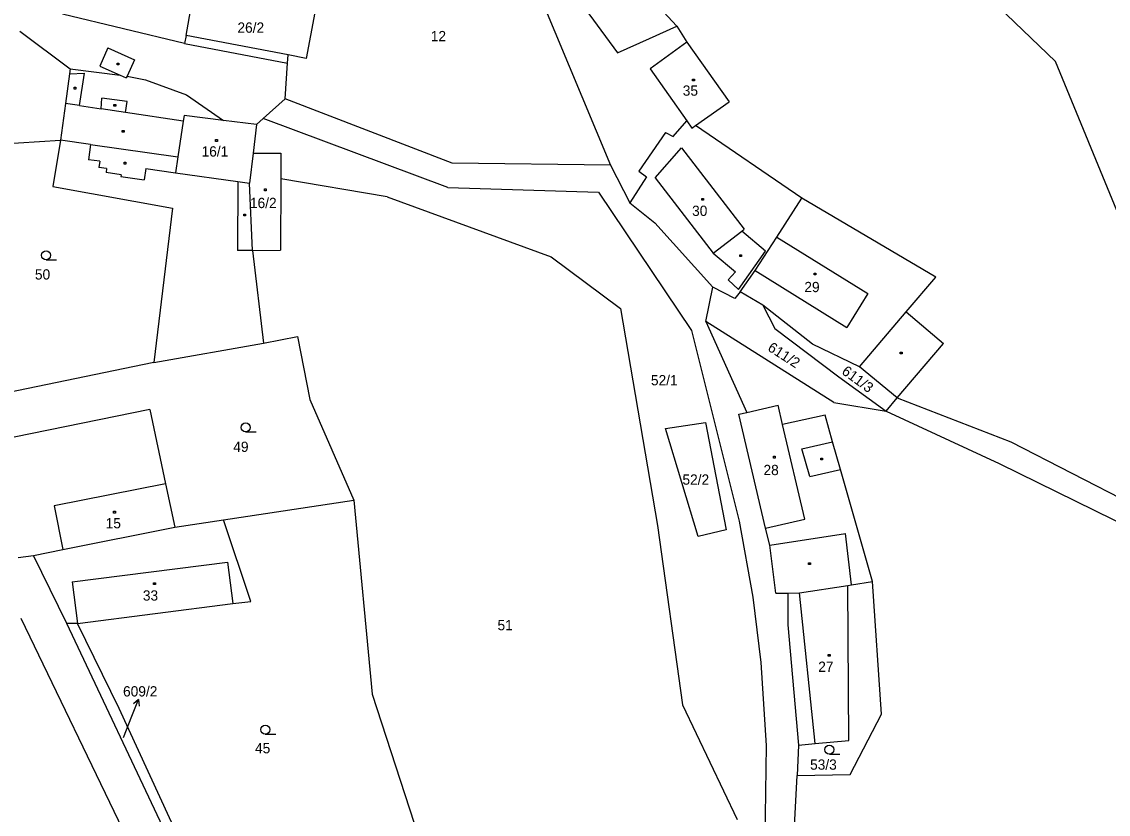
# Model space of a CAD drawing. Extents: x -794421 to -792735, y -1117671 to -1115559.
# Drawn here: x -793289.6 to -793109.5, y -1117055.3 to -1116924 of the extents above; entities that cross this region are included whole.
import ezdxf

# ---------------------------------------------------------------- set-up
doc = ezdxf.new("R2010")
doc.units = 0
for name, color, linetype in [('Komunikace', 7, 'Continuous'), ('Vrstva 1', 7, 'Continuous'), ('Vrstva 14', 7, 'Continuous'), ('Vrstva 15', 7, 'Continuous'), ('Vrstva 16', 7, 'Continuous'), ('Vrstva 2', 7, 'Continuous'), ('Vrstva 23', 7, 'Continuous'), ('Vrstva 25', 7, 'Continuous')]:
    doc.layers.add(name, color=color, linetype=linetype)

msp = doc.modelspace()

# ---------------------------------------------------------------- linework, layer by layer
at = {"layer": 'Komunikace'}
msp.add_line((-793272.71, -1117042.6), (-793271.32, -1117039.06), dxfattribs=at)
at = {"layer": 'Vrstva 1'}
for p, q in [((-793180.98, -1116924.73), (-793191.3, -1116913.51)), ((-793200.57, -1116915.82), (-793190.84, -1116929.15)), ((-793203.93, -1116919.16), (-793192.01, -1116947.74)), ((-793118.24, -1116930.56), (-793129.06, -1116920.12)), ((-793262.33, -1116926.27), (-793261.41, -1116921.2)), ((-793241, -1116922.43), (-793242.42, -1116930.04)), ((-793262.58, -1116927.59), (-793282.79, -1116922.72)), ((-793289.85, -1116925.54), (-793281.55, -1116931.8)), ((-793185.53, -1116926.77), (-793180.98, -1116924.73)), ((-793180.98, -1116924.73), (-793179.36, -1116927.35)), ((-793262.33, -1116926.27), (-793262.58, -1116927.59)), ((-793262.58, -1116927.59), (-793245.52, -1116930.82)), ((-793190.84, -1116929.15), (-793185.53, -1116926.77)), ((-793179.36, -1116927.35), (-793185.44, -1116931.78)), ((-793179.36, -1116927.35), (-793172.35, -1116937.22)), ((-793275.29, -1116928.32), (-793276.62, -1116931.34)), ((-793275.29, -1116928.32), (-793270.88, -1116930.27)), ((-793245.52, -1116930.82), (-793245.43, -1116929.47)), ((-793242.42, -1116930.04), (-793245.43, -1116929.47)), ((-793276.62, -1116931.34), (-793273.25, -1116932.83)), ((-793270.88, -1116930.27), (-793272.1, -1116932.97)), ((-793245.9, -1116936.77), (-793245.52, -1116930.82)), ((-793107.29, -1116957.14), (-793118.24, -1116930.56)), ((-793281.62, -1116932.62), (-793282.31, -1116937.53)), ((-793281.55, -1116931.8), (-793281.62, -1116932.62)), ((-793281.55, -1116931.8), (-793273.25, -1116932.83)), ((-793272.1, -1116932.97), (-793269.06, -1116933.59)), ((-793185.44, -1116931.78), (-793179.36, -1116940.37)), ((-793269.06, -1116933.59), (-793262.27, -1116936.09)), ((-793262.27, -1116936.09), (-793256.1, -1116940.31)), ((-793249.53, -1116940), (-793245.9, -1116936.77)), ((-793218.24, -1116947.4), (-793245.9, -1116936.77)), ((-793282.31, -1116937.53), (-793283.16, -1116943.6)), ((-793177.91, -1116941.15), (-793172.35, -1116937.22)), ((-793250.64, -1116940.98), (-793256.1, -1116940.31)), ((-793250.64, -1116940.98), (-793249.53, -1116940)), ((-793218.93, -1116951.43), (-793249.53, -1116940)), ((-793181.61, -1116943), (-793179.36, -1116940.37)), ((-793179.36, -1116940.37), (-793178.51, -1116941.58)), ((-793250.64, -1116940.98), (-793251.22, -1116945.75)), ((-793178.51, -1116941.58), (-793177.91, -1116941.15)), ((-793160.26, -1116953.21), (-793177.91, -1116941.15)), ((-793313.1, -1116945.43), (-793283.16, -1116943.6)), ((-793283.16, -1116943.6), (-793284.43, -1116951.26)), ((-793182.85, -1116942.31), (-793187.32, -1116948.72)), ((-793182.85, -1116942.31), (-793181.61, -1116943)), ((-793251.22, -1116945.75), (-793251.82, -1116950.7)), ((-793251.22, -1116945.75), (-793246.61, -1116945.77)), ((-793246.61, -1116945.77), (-793246.63, -1116949.98)), ((-793192.01, -1116947.74), (-793218.24, -1116947.4)), ((-793192.01, -1116947.74), (-793188.78, -1116953.98)), ((-793187.32, -1116948.72), (-793186.03, -1116949.69)), ((-793284.43, -1116951.26), (-793264.58, -1116954.85)), ((-793251.29, -1116961.86), (-793251.82, -1116950.7)), ((-793246.63, -1116949.98), (-793246.69, -1116961.83)), ((-793228.99, -1116952.96), (-793246.63, -1116949.98)), ((-793186.03, -1116949.69), (-793188.78, -1116953.98)), ((-793228.99, -1116952.96), (-793201.81, -1116962.93)), ((-793218.93, -1116951.43), (-793193.99, -1116952.19)), ((-793193.99, -1116952.19), (-793178.57, -1116975.15)), ((-793264.58, -1116954.85), (-793267.65, -1116980.42)), ((-793188.78, -1116953.98), (-793184.63, -1116957.3)), ((-793164.45, -1116959.67), (-793160.26, -1116953.21)), ((-793138.07, -1116966.28), (-793160.26, -1116953.21)), ((-793184.63, -1116957.3), (-793175.02, -1116967.94)), ((-793168.03, -1116965.2), (-793164.45, -1116959.67)), ((-793251.29, -1116961.86), (-793246.69, -1116961.83)), ((-793251.29, -1116961.86), (-793249.49, -1116977.21)), ((-793201.81, -1116962.93), (-793190.35, -1116971.51)), ((-793170.49, -1116968.71), (-793168.03, -1116965.2)), ((-793142.98, -1116972.07), (-793138.07, -1116966.28)), ((-793176.21, -1116973.63), (-793175.02, -1116967.94)), ((-793171.36, -1116969.86), (-793175.02, -1116967.94)), ((-793170.49, -1116968.71), (-793171.36, -1116969.86)), ((-793166.76, -1116970.96), (-793170.49, -1116968.71)), ((-793166.76, -1116970.96), (-793164.78, -1116974.83)), ((-793158.54, -1116977.41), (-793166.76, -1116970.96)), ((-793190.35, -1116971.51), (-793184.18, -1117007.46)), ((-793142.98, -1116972.07), (-793136.81, -1116977.3)), ((-793154.97, -1116987.06), (-793176.21, -1116973.63)), ((-793176.21, -1116973.63), (-793169.4, -1116988.71)), ((-793249.49, -1116977.21), (-793243.85, -1116976.13)), ((-793243.85, -1116976.13), (-793241.82, -1116986.55)), ((-793178.57, -1116975.15), (-793170.69, -1117006.74)), ((-793164.78, -1116974.83), (-793154.14, -1116982.84)), ((-793267.65, -1116980.42), (-793249.49, -1116977.21)), ((-793150.71, -1116981.18), (-793158.54, -1116977.41)), ((-793144.47, -1116986.29), (-793136.81, -1116977.3)), ((-793267.65, -1116980.42), (-793302.03, -1116987.53)), ((-793144.47, -1116986.29), (-793150.71, -1116981.18)), ((-793154.14, -1116982.84), (-793146.33, -1116988.51)), ((-793241.82, -1116986.55), (-793234.54, -1117003.23)), ((-793154.97, -1116987.06), (-793146.33, -1116988.51)), ((-793146.33, -1116988.51), (-793144.47, -1116986.29)), ((-793144.47, -1116986.29), (-793125.63, -1116993.61)), ((-793268.31, -1116988.25), (-793299.48, -1116994.56)), ((-793268.31, -1116988.25), (-793265.71, -1117000.56)), ((-793170.72, -1116989.01), (-793169.4, -1116988.71)), ((-793166.29, -1117007.9), (-793170.72, -1116989.01)), ((-793169.4, -1116988.71), (-793164.23, -1116987.53)), ((-793163.49, -1116990.7), (-793164.23, -1116987.53)), ((-793146.33, -1116988.51), (-793127.56, -1116997.16)), ((-793182.9, -1116991.37), (-793176.23, -1116990.4)), ((-793176.23, -1116990.4), (-793172.84, -1117008.19)), ((-793156.44, -1116989.17), (-793163.49, -1116990.7)), ((-793155.19, -1116993.57), (-793156.44, -1116989.17)), ((-793177.47, -1117009.26), (-793182.9, -1116991.37)), ((-793153.88, -1116998.16), (-793155.19, -1116993.57)), ((-793125.63, -1116993.61), (-793102.09, -1117005.68)), ((-793127.56, -1116997.16), (-793103.79, -1117008.89)), ((-793148.59, -1117016.73), (-793153.88, -1116998.16)), ((-793265.71, -1117000.56), (-793264.2, -1117007.7)), ((-793256.15, -1117006.49), (-793234.54, -1117003.23)), ((-793234.54, -1117003.23), (-793231.5, -1117035.41)), ((-793264.2, -1117007.7), (-793256.15, -1117006.49)), ((-793251.62, -1117020.03), (-793256.15, -1117006.49)), ((-793170.69, -1117006.74), (-793168.4, -1117019.3)), ((-793282.74, -1117011.43), (-793264.2, -1117007.7)), ((-793184.18, -1117007.46), (-793180.05, -1117037.18)), ((-793172.84, -1117008.19), (-793177.47, -1117009.26)), ((-793165.58, -1117010.72), (-793166.29, -1117007.9)), ((-793290.15, -1117012.77), (-793287.6, -1117012.41)), ((-793287.6, -1117012.41), (-793282.74, -1117011.43)), ((-793282.07, -1117023.71), (-793287.6, -1117012.41)), ((-793164.61, -1117018.64), (-793165.58, -1117010.72)), ((-793160.65, -1117018.62), (-793152.67, -1117017.38)), ((-793152.67, -1117017.38), (-793152.03, -1117017.28)), ((-793152.52, -1117043.06), (-793152.67, -1117017.38)), ((-793152.03, -1117017.28), (-793148.59, -1117016.73)), ((-793147.08, -1117038.73), (-793148.59, -1117016.73)), ((-793168.4, -1117019.3), (-793167.05, -1117030.13)), ((-793164.61, -1117018.64), (-793162.58, -1117018.64)), ((-793162.58, -1117018.64), (-793160.65, -1117018.62)), ((-793162.58, -1117018.64), (-793162.58, -1117023.89)), ((-793280.3, -1117023.67), (-793254.58, -1117020.4)), ((-793254.58, -1117020.4), (-793251.62, -1117020.03)), ((-793289.72, -1117022.82), (-793271.32, -1117060.97)), ((-793280.3, -1117023.67), (-793282.07, -1117023.71)), ((-793256.81, -1117077.23), (-793282.07, -1117023.71)), ((-793273.41, -1117037.8), (-793280.3, -1117023.67)), ((-793162.58, -1117023.89), (-793160.82, -1117043.84)), ((-793167.05, -1117030.13), (-793166.2, -1117043.88)), ((-793231.5, -1117035.41), (-793223.75, -1117059.17)), ((-793180.05, -1117037.18), (-793171.02, -1117056.17)), ((-793263.29, -1117059.75), (-793273.41, -1117037.8)), ((-793152.29, -1117048.69), (-793147.08, -1117038.73)), ((-793158.1, -1117043.59), (-793152.52, -1117043.06)), ((-793166.2, -1117043.88), (-793166.59, -1117070.61)), ((-793160.82, -1117043.84), (-793161.06, -1117048.89)), ((-793160.82, -1117043.84), (-793158.1, -1117043.59)), ((-793162.08, -1117068.82), (-793161.06, -1117048.89)), ((-793161.06, -1117048.89), (-793152.29, -1117048.69))]:
    msp.add_line(p, q, dxfattribs=at)
at = {"layer": 'Vrstva 16'}
for p, q in [((-793271.32, -1117039.06), (-793270.221, -1117036.268)), ((-793270.221, -1117036.268), (-793271.053, -1117037.015)), ((-793270.221, -1117036.268), (-793270.122, -1117037.381))]:
    msp.add_line(p, q, dxfattribs=at)
at = {"layer": 'Vrstva 2'}
for p, q in [((-793245.43, -1116929.47), (-793262.33, -1116926.27)), ((-793281.62, -1116932.62), (-793279.18, -1116932.47)), ((-793279.98, -1116937.87), (-793279.18, -1116932.47)), ((-793273.25, -1116932.83), (-793272.23, -1116933.28)), ((-793272.1, -1116932.97), (-793272.23, -1116933.28)), ((-793276.41, -1116938.4), (-793276.27, -1116936.62)), ((-793272.07, -1116937.21), (-793276.27, -1116936.62)), ((-793279.98, -1116937.87), (-793282.31, -1116937.53)), ((-793279.98, -1116937.87), (-793276.41, -1116938.4)), ((-793272.34, -1116939.01), (-793276.41, -1116938.4)), ((-793272.34, -1116939.01), (-793272.07, -1116937.21)), ((-793262.78, -1116940.44), (-793272.34, -1116939.01)), ((-793262.78, -1116940.44), (-793263.67, -1116946.37)), ((-793262.66, -1116939.5), (-793262.78, -1116940.44)), ((-793256.1, -1116940.31), (-793262.66, -1116939.5)), ((-793278.14, -1116944.31), (-793283.16, -1116943.6)), ((-793278.14, -1116944.31), (-793278.5, -1116946.83)), ((-793278.14, -1116944.31), (-793263.67, -1116946.37)), ((-793184.56, -1116949.82), (-793180.24, -1116944.89)), ((-793180.24, -1116944.89), (-793169.83, -1116958.35)), ((-793276.64, -1116947.09), (-793278.5, -1116946.83)), ((-793276.64, -1116947.09), (-793276.78, -1116948.1)), ((-793263.67, -1116946.37), (-793264.06, -1116948.99)), ((-793275.49, -1116948.28), (-793276.78, -1116948.1)), ((-793275.49, -1116948.28), (-793275.59, -1116948.97)), ((-793273.07, -1116949.32), (-793275.59, -1116948.97)), ((-793273.07, -1116949.32), (-793273.11, -1116949.62)), ((-793269.01, -1116948.3), (-793269.27, -1116950.15)), ((-793269.01, -1116948.3), (-793264.06, -1116948.99)), ((-793264.06, -1116948.99), (-793253.77, -1116950.43)), ((-793273.11, -1116949.62), (-793269.27, -1116950.15)), ((-793253.77, -1116950.43), (-793253.81, -1116961.88)), ((-793253.77, -1116950.43), (-793251.82, -1116950.7)), ((-793184.56, -1116949.82), (-793174.96, -1116962.3)), ((-793170.23, -1116958.66), (-793169.83, -1116958.35)), ((-793174.96, -1116962.3), (-793170.23, -1116958.66)), ((-793166.29, -1116961.97), (-793170.23, -1116958.66)), ((-793164.45, -1116959.67), (-793149.37, -1116969.02)), ((-793251.29, -1116961.86), (-793253.81, -1116961.88)), ((-793170.79, -1116968.34), (-793166.29, -1116961.97)), ((-793174.96, -1116962.3), (-793171.28, -1116965.44)), ((-793172.5, -1116966.76), (-793171.28, -1116965.44)), ((-793168.03, -1116965.2), (-793152.84, -1116974.62)), ((-793170.79, -1116968.34), (-793172.5, -1116966.76)), ((-793149.37, -1116969.02), (-793152.84, -1116974.62)), ((-793150.71, -1116981.18), (-793142.98, -1116972.07)), ((-793159.8, -1117006.38), (-793163.49, -1116990.7)), ((-793160.26, -1116994.73), (-793155.19, -1116993.57)), ((-793158.95, -1116999.32), (-793160.26, -1116994.73)), ((-793158.95, -1116999.32), (-793153.88, -1116998.16)), ((-793265.71, -1117000.56), (-793284.19, -1117004.19)), ((-793284.19, -1117004.19), (-793282.74, -1117011.43)), ((-793166.29, -1117007.9), (-793159.8, -1117006.38)), ((-793165.58, -1117010.72), (-793153.07, -1117008.79)), ((-793152.03, -1117017.28), (-793153.07, -1117008.79)), ((-793281.18, -1117016.78), (-793255.46, -1117013.51)), ((-793255.46, -1117013.51), (-793254.58, -1117020.4)), ((-793281.18, -1117016.78), (-793280.3, -1117023.67)), ((-793158.1, -1117043.59), (-793160.65, -1117018.62))]:
    msp.add_line(p, q, dxfattribs=at)
at = {"layer": 'Vrstva 23'}
for p, q in [((-793285.52, -1116963.43), (-793283.77, -1116963.43)), ((-793252.46, -1116991.95), (-793250.71, -1116991.95)), ((-793249.19, -1117042.03), (-793247.44, -1117042.03)), ((-793155.71, -1117045.34), (-793153.96, -1117045.34))]:
    msp.add_line(p, q, dxfattribs=at)
for centre in [(-793285.52, -1116962.68), (-793252.46, -1116991.2), (-793249.19, -1117041.28), (-793155.71, -1117044.59)]:
    msp.add_circle(centre, 0.75, dxfattribs=at)
at = {"layer": 'Vrstva 25'}
for p, q in [((-793273.77, -1116930.82), (-793273.47, -1116930.82)), ((-793273.77, -1116931.12), (-793273.77, -1116930.82)), ((-793273.47, -1116931.12), (-793273.77, -1116931.12)), ((-793273.47, -1116930.82), (-793273.47, -1116931.12)), ((-793280.88, -1116934.84), (-793280.58, -1116934.84)), ((-793280.88, -1116935.14), (-793280.88, -1116934.84)), ((-793280.58, -1116934.84), (-793280.58, -1116935.14)), ((-793178.39, -1116933.49), (-793178.09, -1116933.49)), ((-793178.39, -1116933.79), (-793178.39, -1116933.49)), ((-793178.09, -1116933.79), (-793178.39, -1116933.79)), ((-793178.09, -1116933.49), (-793178.09, -1116933.79)), ((-793280.58, -1116935.14), (-793280.88, -1116935.14)), ((-793274.28, -1116937.68), (-793273.98, -1116937.68)), ((-793274.28, -1116937.98), (-793274.28, -1116937.68)), ((-793273.98, -1116937.98), (-793274.28, -1116937.98)), ((-793273.98, -1116937.68), (-793273.98, -1116937.98)), ((-793272.89, -1116941.99), (-793272.59, -1116941.99)), ((-793272.89, -1116942.29), (-793272.89, -1116941.99)), ((-793272.59, -1116941.99), (-793272.59, -1116942.29)), ((-793272.59, -1116942.29), (-793272.89, -1116942.29)), ((-793257.43, -1116943.49), (-793257.13, -1116943.49)), ((-793257.43, -1116943.79), (-793257.43, -1116943.49)), ((-793257.13, -1116943.79), (-793257.43, -1116943.79)), ((-793257.13, -1116943.49), (-793257.13, -1116943.79)), ((-793272.6, -1116947.26), (-793272.3, -1116947.26)), ((-793272.6, -1116947.56), (-793272.6, -1116947.26)), ((-793272.3, -1116947.56), (-793272.6, -1116947.56)), ((-793272.3, -1116947.26), (-793272.3, -1116947.56)), ((-793249.34, -1116951.68), (-793249.04, -1116951.68)), ((-793249.34, -1116951.98), (-793249.34, -1116951.68)), ((-793249.04, -1116951.98), (-793249.34, -1116951.98)), ((-793249.04, -1116951.68), (-793249.04, -1116951.98)), ((-793176.87, -1116953.26), (-793176.57, -1116953.26)), ((-793176.87, -1116953.56), (-793176.87, -1116953.26)), ((-793176.57, -1116953.56), (-793176.87, -1116953.56)), ((-793176.57, -1116953.26), (-793176.57, -1116953.56)), ((-793252.78, -1116955.86), (-793252.48, -1116955.86)), ((-793252.78, -1116956.16), (-793252.78, -1116955.86)), ((-793252.48, -1116956.16), (-793252.78, -1116956.16)), ((-793252.48, -1116955.86), (-793252.48, -1116956.16)), ((-793170.56, -1116962.6), (-793170.26, -1116962.6)), ((-793170.56, -1116962.9), (-793170.56, -1116962.6)), ((-793170.26, -1116962.9), (-793170.56, -1116962.9)), ((-793170.26, -1116962.6), (-793170.26, -1116962.9)), ((-793158.24, -1116965.62), (-793157.94, -1116965.62)), ((-793158.24, -1116965.92), (-793158.24, -1116965.62)), ((-793157.94, -1116965.62), (-793157.94, -1116965.92)), ((-793157.94, -1116965.92), (-793158.24, -1116965.92)), ((-793143.98, -1116978.73), (-793143.68, -1116978.73)), ((-793143.98, -1116979.03), (-793143.98, -1116978.73)), ((-793143.68, -1116979.03), (-793143.98, -1116979.03)), ((-793143.68, -1116978.73), (-793143.68, -1116979.03)), ((-793165, -1116995.97), (-793164.7, -1116995.97)), ((-793165, -1116996.27), (-793165, -1116995.97)), ((-793164.7, -1116996.27), (-793165, -1116996.27)), ((-793164.7, -1116995.97), (-793164.7, -1116996.27)), ((-793157.14, -1116996.28), (-793156.84, -1116996.28)), ((-793157.14, -1116996.58), (-793157.14, -1116996.28)), ((-793156.84, -1116996.28), (-793156.84, -1116996.58)), ((-793156.84, -1116996.58), (-793157.14, -1116996.58)), ((-793274.33, -1117005.1), (-793274.03, -1117005.1)), ((-793274.33, -1117005.4), (-793274.33, -1117005.1)), ((-793274.03, -1117005.1), (-793274.03, -1117005.4)), ((-793274.03, -1117005.4), (-793274.33, -1117005.4)), ((-793159.15, -1117013.62), (-793158.85, -1117013.62)), ((-793159.15, -1117013.92), (-793159.15, -1117013.62)), ((-793158.85, -1117013.92), (-793159.15, -1117013.92)), ((-793158.85, -1117013.62), (-793158.85, -1117013.92)), ((-793267.7, -1117016.94), (-793267.4, -1117016.94)), ((-793267.7, -1117017.24), (-793267.7, -1117016.94)), ((-793267.4, -1117017.24), (-793267.7, -1117017.24)), ((-793267.4, -1117016.94), (-793267.4, -1117017.24)), ((-793155.91, -1117028.8), (-793155.61, -1117028.8)), ((-793155.91, -1117029.1), (-793155.91, -1117028.8)), ((-793155.61, -1117029.1), (-793155.91, -1117029.1)), ((-793155.61, -1117028.8), (-793155.61, -1117029.1))]:
    msp.add_line(p, q, dxfattribs=at)

# ---------------------------------------------------------------- texts
at = {"layer": 'Vrstva 14'}
for s, height, p in [('12', 1.7, (-793221.77, -1116927.2)), ('50', 1.7, (-793287.372, -1116966.69)), ('52/1', 1.7, (-793185.289, -1116984.22)), ('49', 1.7, (-793254.503, -1116995.25)), ('52/2', 1.7, (-793180.066, -1117000.69)), ('51', 1.7, (-793210.716, -1117024.81)), ('609/2', 0.1, (-793272.915, -1117042.6)), ('45', 1.7, (-793250.899, -1117045.2)), ('53/3', 1.7, (-793158.916, -1117047.92))]:
    msp.add_text(s, height=height, dxfattribs=at).set_placement(p)
for s, rotation, p in [('611/2', 327.36654, (-793166.08, -1116978.373)), ('611/3', 323.80965, (-793153.811, -1116982.206))]:
    msp.add_text(s, height=1.7, rotation=rotation, dxfattribs=at).set_placement(p)
at = {"layer": 'Vrstva 15'}
for s, p in [('26/2', (-793253.81, -1116925.79)), ('35', (-793180.013, -1116936.23)), ('16/1', (-793259.757, -1116946.31)), ('16/2', (-793251.743, -1116954.85)), ('30', (-793178.466, -1116956.15)), ('29', (-793159.867, -1116968.78)), ('28', (-793166.636, -1116999.1)), ('15', (-793275.646, -1117007.92)), ('33', (-793269.487, -1117019.89)), ('27', (-793157.563, -1117031.7))]:
    msp.add_text(s, height=1.7, dxfattribs=at).set_placement(p)
at = {"layer": 'Vrstva 16'}
msp.add_text('609/2', height=1.7, dxfattribs=at).set_placement((-793272.77, -1117035.78))

doc.saveas('drawing.dxf')
